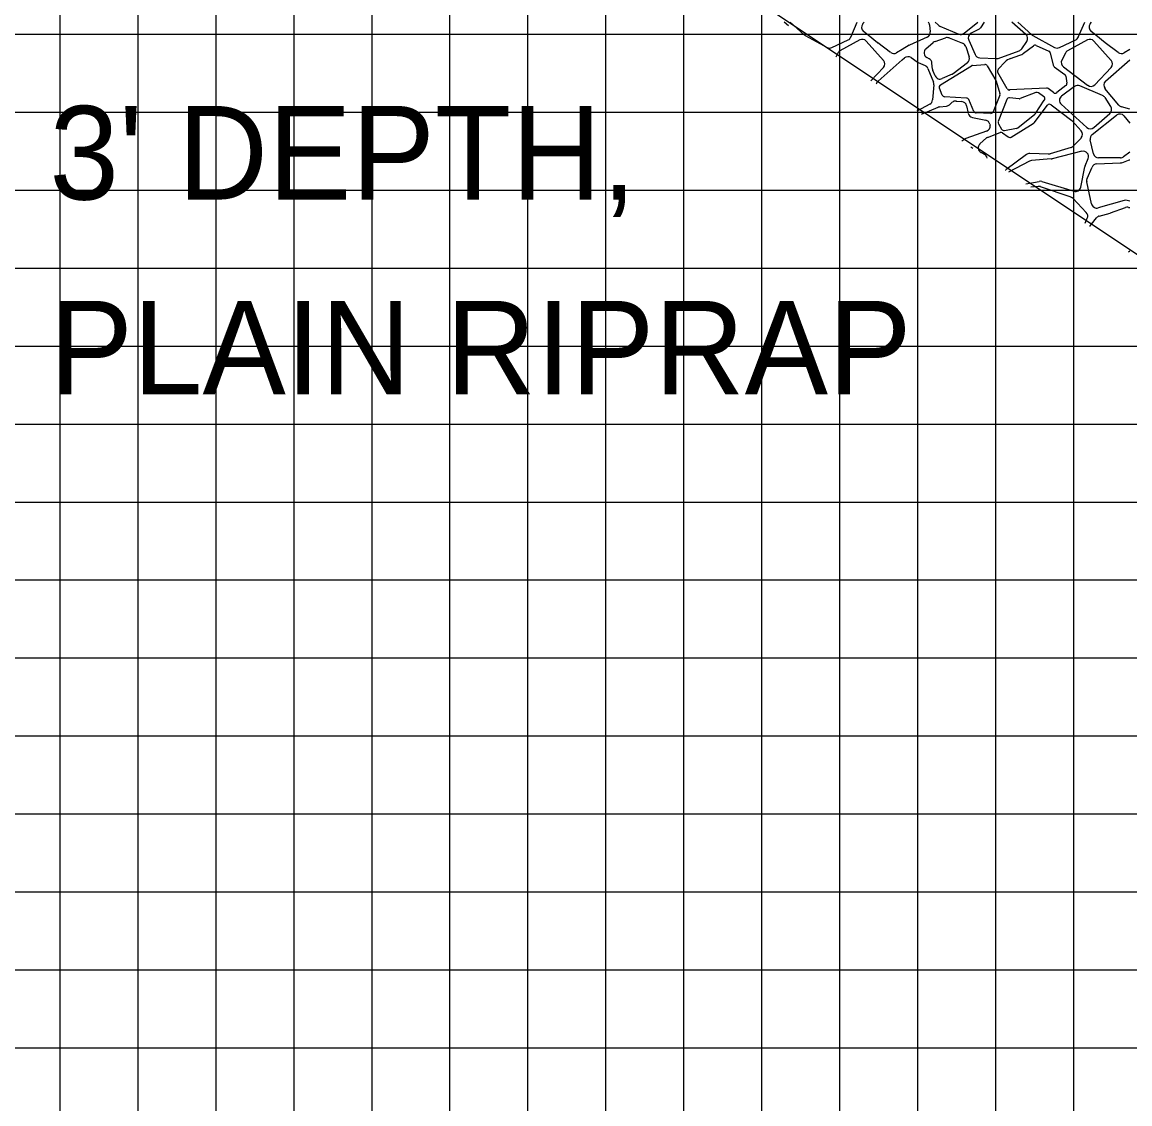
# Model space of a CAD drawing. Extents: x 1770448 to 1770792, y 442591 to 442811.
# Drawn here: x 1770533.55 to 1770547.76, y 442620.95 to 442634.82 of the extents above; entities that cross this region are included whole.
import ezdxf

# ---------------------------------------------------------------- set-up
doc = ezdxf.new("R2010")
doc.units = 0
for name, color, linetype in [('ANNOTATION', 7, 'Continuous'), ('D_Text_Standard', 7, 'Continuous'), ('GRUBBING IN FILL', 7, 'Continuous'), ('MAJOR', 7, 'Continuous'), ('MINOR', 7, 'Continuous')]:
    doc.layers.add(name, color=color, linetype=linetype)

msp = doc.modelspace()

# ---------------------------------------------------------------- linework, layer by layer
at = {"layer": 'ANNOTATION'}
msp.add_lwpolyline([(1770578.203, 442611.606), (1770524.472, 442647.426), (1770523.442, 442648.037), (1770522.53, 442648.443), (1770521.67, 442648.698), (1770521.011, 442648.796)], dxfattribs=at)
at = {"layer": 'GRUBBING IN FILL'}
for p, q in [((1770543.381, 442634.773), (1770543.327, 442634.819)), ((1770543.404, 442634.819), (1770543.585, 442634.657)), ((1770544.182, 442634.627), (1770544.264, 442634.819)), ((1770544.334, 442634.796), (1770544.352, 442634.819)), ((1770544.405, 442634.652), (1770544.345, 442634.7)), ((1770545.192, 442634.784), (1770545.2, 442634.693)), ((1770545.264, 442634.819), (1770545.301, 442634.783)), ((1770545.323, 442634.768), (1770545.567, 442634.667)), ((1770545.636, 442634.677), (1770545.813, 442634.819)), ((1770545.819, 442634.723), (1770545.727, 442634.677)), ((1770545.894, 442634.819), (1770545.845, 442634.746)), ((1770546.426, 442634.661), (1770546.246, 442634.819)), ((1770546.323, 442634.819), (1770546.504, 442634.657)), ((1770547.1, 442634.627), (1770547.183, 442634.819)), ((1770547.253, 442634.796), (1770547.271, 442634.819)), ((1770547.324, 442634.652), (1770547.264, 442634.7)), ((1770543.598, 442634.648), (1770543.877, 442634.495)), ((1770543.939, 442634.493), (1770544.148, 442634.593)), ((1770544.298, 442634.591), (1770544.043, 442634.451)), ((1770544.602, 442634.329), (1770544.381, 442634.576)), ((1770544.525, 442634.555), (1770544.406, 442634.652)), ((1770544.693, 442634.43), (1770544.527, 442634.553)), ((1770545.16, 442634.625), (1770544.937, 442634.525)), ((1770545.144, 442634.476), (1770545.24, 442634.56)), ((1770545.263, 442634.573), (1770545.397, 442634.618)), ((1770545.443, 442634.617), (1770545.616, 442634.55)), ((1770545.695, 442634.589), (1770545.776, 442634.403)), ((1770546.375, 442634.478), (1770546.438, 442634.572)), ((1770546.516, 442634.648), (1770546.796, 442634.495)), ((1770546.858, 442634.493), (1770547.067, 442634.593)), ((1770547.216, 442634.591), (1770546.962, 442634.451)), ((1770547.521, 442634.329), (1770547.3, 442634.576)), ((1770547.444, 442634.555), (1770547.324, 442634.652)), ((1770547.612, 442634.43), (1770547.446, 442634.553)), ((1770544.015, 442634.421), (1770543.988, 442634.368)), ((1770544.842, 442634.47), (1770544.769, 442634.426)), ((1770544.93, 442634.522), (1770544.842, 442634.47)), ((1770545.656, 442634.508), (1770545.702, 442634.374)), ((1770546.074, 442634.355), (1770546.342, 442634.452)), ((1770546.397, 442634.421), (1770546.524, 442634.515)), ((1770546.558, 442634.519), (1770546.721, 442634.447)), ((1770546.74, 442634.424), (1770546.778, 442634.268)), ((1770546.934, 442634.421), (1770546.889, 442634.333)), ((1770547.761, 442634.47), (1770547.687, 442634.426)), ((1770544.531, 442634.062), (1770544.842, 442634.335)), ((1770544.842, 442634.335), (1770544.87, 442634.36)), ((1770544.955, 442634.364), (1770545.033, 442634.309)), ((1770545.045, 442634.302), (1770545.134, 442634.263)), ((1770545.187, 442634.348), (1770545.157, 442634.364)), ((1770545.23, 442634.217), (1770545.223, 442634.294)), ((1770545.678, 442634.298), (1770545.494, 442634.158)), ((1770545.745, 442634.264), (1770545.9, 442634.277)), ((1770545.835, 442634.363), (1770546.047, 442634.351)), ((1770546.074, 442634.214), (1770546.162, 442634.309)), ((1770546.231, 442634.355), (1770546.351, 442634.396)), ((1770547.45, 442634.062), (1770547.761, 442634.335)), ((1770544.44, 442634.068), (1770544.601, 442634.237)), ((1770545.17, 442634.226), (1770545.244, 442634.048)), ((1770545.264, 442634.13), (1770545.236, 442634.197)), ((1770545.332, 442634.014), (1770545.73, 442634.259)), ((1770545.48, 442634.151), (1770545.355, 442634.095)), ((1770545.932, 442634.26), (1770546.044, 442634.07)), ((1770546.188, 442633.966), (1770546.07, 442634.174)), ((1770546.791, 442634.248), (1770546.926, 442634.149)), ((1770546.909, 442634.248), (1770547.22, 442634.01)), ((1770546.94, 442634.127), (1770546.953, 442634.038)), ((1770547.311, 442634.017), (1770547.52, 442634.237)), ((1770545.249, 442634.016), (1770545.231, 442633.821)), ((1770546.047, 442634.063), (1770546.095, 442633.905)), ((1770546.94, 442634.006), (1770546.823, 442633.915)), ((1770547.051, 442633.994), (1770546.886, 442633.871)), ((1770547.412, 442633.878), (1770547.119, 442634.003)), ((1770545.355, 442633.883), (1770545.318, 442633.972)), ((1770545.667, 442633.845), (1770545.385, 442633.862)), ((1770546.094, 442633.882), (1770546.009, 442633.67)), ((1770546.691, 442633.974), (1770546.219, 442633.949)), ((1770546.34, 442633.837), (1770546.219, 442633.849)), ((1770546.557, 442633.915), (1770546.355, 442633.839)), ((1770546.655, 442633.867), (1770546.588, 442633.911)), ((1770546.781, 442633.915), (1770546.714, 442633.967)), ((1770547.619, 442633.755), (1770547.442, 442633.967)), ((1770547.517, 442633.737), (1770547.443, 442633.852)), ((1770545.195, 442633.766), (1770545.027, 442633.677)), ((1770545.109, 442633.647), (1770545.302, 442633.727)), ((1770545.32, 442633.732), (1770545.411, 442633.743)), ((1770545.447, 442633.759), (1770545.484, 442633.791)), ((1770545.535, 442633.807), (1770545.608, 442633.8)), ((1770545.668, 442633.747), (1770545.689, 442633.65)), ((1770545.762, 442633.675), (1770545.696, 442633.825)), ((1770546.184, 442633.827), (1770546.074, 442633.543)), ((1770546.532, 442633.528), (1770546.704, 442633.753)), ((1770546.55, 442633.648), (1770546.664, 442633.82)), ((1770546.752, 442633.759), (1770547.018, 442633.556)), ((1770546.881, 442633.766), (1770547.209, 442633.469)), ((1770547.761, 442633.705), (1770547.654, 442633.733)), ((1770545.742, 442633.597), (1770545.912, 442633.562)), ((1770545.977, 442633.649), (1770545.792, 442633.655)), ((1770546.324, 442633.465), (1770546.543, 442633.641)), ((1770547.276, 442633.377), (1770547.591, 442633.627)), ((1770547.299, 442633.468), (1770547.505, 442633.648)), ((1770547.686, 442633.617), (1770547.761, 442633.525)), ((1770545.924, 442633.42), (1770545.657, 442633.326)), ((1770545.965, 442633.511), (1770545.968, 442633.5)), ((1770546.077, 442633.513), (1770546.117, 442633.446)), ((1770546.152, 442633.429), (1770546.309, 442633.458)), ((1770546.238, 442633.346), (1770546.523, 442633.52)), ((1770547.022, 442633.552), (1770547.137, 442633.427)), ((1770545.643, 442633.319), (1770545.604, 442633.294)), ((1770545.839, 442633.257), (1770545.924, 442633.334)), ((1770545.935, 442633.341), (1770546.096, 442633.403)), ((1770546.129, 442633.399), (1770546.201, 442633.348)), ((1770547.137, 442633.333), (1770547.039, 442633.231)), ((1770547.295, 442633.131), (1770547.252, 442633.308)), ((1770545.896, 442633.123), (1770545.853, 442633.146)), ((1770546.717, 442633.127), (1770546.477, 442633.134)), ((1770547.009, 442633.212), (1770546.739, 442633.13)), ((1770547.147, 442633.163), (1770546.764, 442633.068)), ((1770547.761, 442633.152), (1770547.68, 442633.092)), ((1770545.932, 442633.075), (1770545.932, 442633.076)), ((1770546.434, 442633.12), (1770546.172, 442632.923)), ((1770546.475, 442633.037), (1770546.204, 442632.894)), ((1770546.753, 442633.066), (1770546.501, 442633.045)), ((1770547.187, 442632.975), (1770547.226, 442633.07)), ((1770547.336, 442633), (1770547.638, 442633.013)), ((1770547.64, 442633.079), (1770547.361, 442633.079)), ((1770547.658, 442633.017), (1770547.742, 442633.047)), ((1770547.131, 442632.702), (1770547.183, 442632.962)), ((1770547.213, 442632.815), (1770547.277, 442632.96)), ((1770546.427, 442632.746), (1770546.599, 442632.777)), ((1770546.585, 442632.712), (1770546.493, 442632.702)), ((1770547.007, 442632.574), (1770546.615, 442632.709)), ((1770546.631, 442632.775), (1770547.045, 442632.65)), ((1770547.271, 442632.488), (1770547.208, 442632.773)), ((1770547.202, 442632.379), (1770547.034, 442632.556)), ((1770547.69, 442632.533), (1770547.356, 442632.437)), ((1770547.515, 442632.373), (1770547.707, 442632.441)), ((1770547.761, 442632.523), (1770547.728, 442632.533)), ((1770547.742, 442632.444), (1770547.761, 442632.441)), ((1770547.187, 442632.24), (1770547.215, 442632.305)), ((1770547.271, 442632.229), (1770547.333, 442632.309)), ((1770547.369, 442632.333), (1770547.51, 442632.371)), ((1770547.253, 442632.206), (1770547.271, 442632.229)), ((1770547.761, 442631.88), (1770547.744, 442631.87))]:
    msp.add_line(p, q, dxfattribs=at)
for centre, major_axis, start_param, end_param in [((1770544.388, 442634.754), (0, -0.0683), 4.048343, 5.608444), ((1770545.132, 442634.687), (0, 0.0683), 3.559817, 4.803049), ((1770545.124, 442634.778), (0, 0.0683), 4.803049, 5.35086), ((1770545.349, 442634.831), (0, -0.0683), 5.497787, 5.893869), ((1770545.788, 442634.784), (0, -0.0683), 0.463648, 0.97362), ((1770547.306, 442634.754), (0, -0.0683), 4.048343, 5.608444), ((1770543.63, 442634.708), (0, -0.0683), 5.554357, 5.782172), ((1770544.119, 442634.654), (0, -0.0683), 0.443382, 1.163165), ((1770544.33, 442634.531), (0, 0.0683), 5.44252, 6.785098), ((1770544.363, 442634.599), (0, 0.0683), 5.600869, 5.608444), ((1770544.568, 442634.608), (0, -0.0683), 5.600869, 5.645637), ((1770545.285, 442634.508), (0, 0.0683), 0.321751, 0.71883), ((1770545.418, 442634.553), (0, 0.0683), 5.917129, 6.604936), ((1770545.593, 442634.73), (0, -0.0683), 5.893869, 6.957926), ((1770545.592, 442634.486), (0, 0.0683), 5.039487, 5.917129), ((1770545.757, 442634.616), (0, 0.0683), 0.463648, 1.985303), ((1770546.382, 442634.61), (0, -0.0683), 0.977446, 2.424153), ((1770546.549, 442634.708), (0, -0.0683), 5.554357, 5.782172), ((1770547.038, 442634.654), (0, -0.0683), 0.443382, 1.163165), ((1770547.249, 442634.531), (0, 0.0683), 5.44252, 6.785098), ((1770547.281, 442634.599), (0, 0.0683), 5.600869, 5.608444), ((1770547.487, 442634.608), (0, -0.0683), 5.600869, 5.645637), ((1770543.91, 442634.555), (0, -0.0683), 5.782172, 6.726567), ((1770544.076, 442634.391), (0, 0.0683), 0.501913, 1.108164), ((1770544.734, 442634.485), (0, -0.0683), 5.645637, 6.81814), ((1770544.965, 442634.463), (0, 0.0683), 0.418224, 0.534955), ((1770545.189, 442634.425), (0, -0.0683), 3.860423, 5.799738), ((1770546.318, 442634.516), (0, -0.0683), 0.347767, 0.977446), ((1770546.295, 442634.557), (0, -0.171), 0.333945, 0.641659), ((1770546.544, 442634.488), (0, 0.0342), 5.866747, 6.924845), ((1770546.707, 442634.416), (0, 0.0342), 4.95256, 5.866747), ((1770546.829, 442634.555), (0, -0.0683), 5.782172, 6.726567), ((1770546.995, 442634.391), (0, 0.0683), 0.501913, 1.108164), ((1770547.653, 442634.485), (0, -0.0683), 5.645637, 6.81814), ((1770544.551, 442634.284), (0, -0.0683), 0.810393, 2.300927), ((1770544.915, 442634.308), (0, 0.0683), 5.668522, 7.003256), ((1770545.073, 442634.365), (0, -0.0683), 5.668522, 5.870775), ((1770545.155, 442634.288), (0, 0.0683), 4.803049, 5.799738), ((1770545.637, 442634.352), (0, 0.0683), 3.787712, 5.039487), ((1770545.747, 442634.23), (0, 0.0342), 0.081452, 0.550676), ((1770545.839, 442634.431), (0, -0.0683), 5.126896, 6.226907), ((1770545.903, 442634.243), (0, 0.0342), 5.244893, 6.364637), ((1770546.051, 442634.419), (0, -0.0683), 6.226907, 6.630952), ((1770546.287, 442634.193), (0, 0.171), 0.333945, 0.825917), ((1770546.811, 442634.276), (0, -0.0342), 4.95256, 5.649393), ((1770546.95, 442634.302), (0, 0.0683), 1.108164, 2.48948), ((1770547.47, 442634.284), (0, -0.0683), 0.810393, 2.300927), ((1770545.107, 442634.2), (0, 0.0683), 5.104729, 5.870775), ((1770545.298, 442634.224), (0, -0.0683), 4.803049, 5.120538), ((1770545.327, 442634.157), (0, -0.0683), 5.120538, 6.699624), ((1770545.453, 442634.213), (0, -0.0683), 0.416439, 0.646119), ((1770546.099, 442634.19), (0, -0.0342), 3.967509, 5.232357), ((1770546.906, 442634.121), (0, 0.0342), 4.865038, 5.649393), ((1770544.576, 442634.011), (0, -0.0683), 3.861663, 4.542823), ((1770545.181, 442634.022), (0, 0.0683), 4.621729, 5.104729), ((1770545.349, 442633.985), (0, -0.0342), 3.692268, 5.10718), ((1770546.014, 442634.053), (0, 0.0342), 5.00783, 5.244893), ((1770546.92, 442634.033), (0, 0.0342), 3.796699, 4.865038), ((1770547.092, 442633.94), (0, 0.0683), 5.881372, 6.922099), ((1770547.262, 442634.064), (0, -0.0683), 5.631073, 7.093578), ((1770547.495, 442634.011), (0, -0.0683), 3.861663, 5.40978), ((1770545.387, 442633.896), (0, -0.0342), 5.10718, 6.225111), ((1770545.665, 442633.811), (0, 0.0342), 5.126896, 6.225111), ((1770546.062, 442633.895), (0, 0.0342), 4.331883, 5.00783), ((1770546.215, 442633.815), (0, 0.0342), 6.185932, 7.487587), ((1770546.218, 442633.983), (0, -0.0342), 5.232357, 6.335377), ((1770546.343, 442633.871), (0, -0.0342), 6.185932, 6.640689), ((1770546.569, 442633.883), (0, 0.0342), 5.695183, 6.640689), ((1770546.636, 442633.838), (0, -0.0342), 0.982794, 2.55359), ((1770546.693, 442633.94), (0, 0.0342), 5.62749, 6.335377), ((1770546.802, 442633.942), (0, -0.0342), 5.62749, 6.938291), ((1770546.926, 442633.816), (0, 0.0683), 0.638914, 2.406418), ((1770547.385, 442633.815), (0, 0.0683), 5.287694, 5.881372), ((1770545.163, 442633.827), (0, -0.0683), 0.489957, 1.480136), ((1770545.328, 442633.664), (0, 0.0683), 0.124355, 0.394791), ((1770545.402, 442633.811), (0, -0.0683), 0.124355, 0.704494), ((1770545.529, 442633.739), (0, 0.0683), 6.183517, 6.987679), ((1770545.601, 442633.732), (0, 0.0683), 4.928939, 6.183517), ((1770546.731, 442633.732), (0, 0.0342), 5.630339, 7.201135), ((1770547.46, 442633.7), (0, -0.0683), 0.719883, 2.146101), ((1770547.672, 442633.799), (0, -0.0683), 5.40978, 6.025862), ((1770545.136, 442633.584), (0, 0.0683), 0.394791, 0.726629), ((1770545.756, 442633.664), (0, -0.0683), 4.928939, 6.08014), ((1770545.793, 442633.689), (0, -0.0342), 5.126896, 6.25041), ((1770545.899, 442633.495), (0, 0.0683), 4.941621, 6.08014), ((1770545.978, 442633.683), (0, -0.0342), 6.25041, 7.473475), ((1770546.522, 442633.667), (0, -0.0342), 0.676737, 0.982794), ((1770546.997, 442633.529), (0, 0.0342), 5.459199, 5.630339), ((1770547.633, 442633.573), (0, 0.0683), 5.401291, 6.952921), ((1770545.901, 442633.484), (0, 0.0683), 3.480291, 4.941621), ((1770546.106, 442633.53), (0, 0.0342), 1.204402, 2.105751), ((1770546.146, 442633.463), (0, -0.0342), 5.247344, 6.461278), ((1770546.303, 442633.491), (0, -0.0342), 0.178093, 0.676737), ((1770546.505, 442633.549), (0, -0.0342), 0.547562, 0.91795), ((1770547.087, 442633.381), (0, 0.0683), 3.950796, 5.459199), ((1770547.254, 442633.519), (0, -0.0683), 5.54801, 7.003068), ((1770545.68, 442633.261), (0, 0.0683), 0.338698, 0.570383), ((1770545.947, 442633.309), (0, 0.0342), 0.369906, 0.736656), ((1770546.109, 442633.372), (0, 0.0342), 5.662936, 6.653091), ((1770546.221, 442633.375), (0, -0.0342), 5.662936, 6.830748), ((1770547.319, 442633.324), (0, -0.0683), 3.811328, 4.949439), ((1770545.698, 442633.151), (0, 0.0683), 5.469865, 5.923398), ((1770545.885, 442633.206), (0, -0.0683), 3.878249, 5.800672), ((1770546.475, 442633.066), (0, 0.0683), 6.255795, 6.928761), ((1770546.719, 442633.196), (0, -0.0683), 6.255795, 6.578122), ((1770546.989, 442633.278), (0, -0.0683), 0.294937, 0.809203), ((1770547.163, 442633.096), (0, -0.0683), 1.177705, 3.383486), ((1770547.361, 442633.147), (0, -0.0683), 4.949439, 6.284735), ((1770545.865, 442633.063), (0, 0.0683), 4.915434, 5.800672), ((1770546.507, 442632.977), (0, 0.0683), 0.083141, 0.485227), ((1770546.747, 442633.134), (0, -0.0683), 0.083141, 0.241894), ((1770547.339, 442632.932), (0, 0.0683), 0.042528, 1.152572), ((1770547.635, 442633.082), (0, -0.0683), 0.042528, 0.339293), ((1770547.64, 442633.147), (0, -0.0683), 0.001549, 0.632145), ((1770547.764, 442632.982), (0, 0.0683), 0.046753, 0.339293), ((1770546.131, 442632.977), (0, -0.0683), 0.549654, 0.645576), ((1770547.25, 442632.949), (0, 0.0683), 1.177705, 1.37369), ((1770546.593, 442632.645), (0, 0.0683), 5.950458, 6.397059), ((1770546.611, 442632.71), (0, 0.0683), 5.991139, 6.460411), ((1770547.064, 442632.716), (0, -0.0683), 5.991139, 7.656876), ((1770547.275, 442632.788), (0, -0.0683), 4.294165, 4.928939), ((1770546.984, 442632.509), (0, 0.0683), 5.472885, 5.950458), ((1770547.337, 442632.503), (0, -0.0683), 4.928939, 6.561485), ((1770547.709, 442632.467), (0, 0.0683), 6.004886, 6.561485), ((1770547.73, 442632.377), (0, 0.0683), 6.110994, 6.626209), ((1770547.153, 442632.332), (0, -0.0683), 1.163165, 2.331293), ((1770547.387, 442632.267), (0, 0.0683), 0.266252, 0.90675), ((1770547.492, 442632.437), (0, -0.0683), 0.266252, 0.343024), ((1770547.306, 442632.164), (0, -0.0683), 4.048343, 4.166099)]:
    msp.add_ellipse(centre, major_axis=major_axis, ratio=0.99895, start_param=start_param, end_param=end_param, dxfattribs=at)
at = {"layer": 'MAJOR'}
for p, q in [((1770534.041, 442608.665), (1770534.041, 442658.665)), ((1770544.041, 442608.665), (1770544.041, 442658.665)), ((1770474.041, 442633.665), (1770754.041, 442633.665)), ((1770474.041, 442628.665), (1770754.041, 442628.665)), ((1770474.041, 442623.665), (1770754.041, 442623.665))]:
    msp.add_line(p, q, dxfattribs=at)
at = {"layer": 'MINOR'}
for p, q in [((1770535.041, 442608.665), (1770535.041, 442658.665)), ((1770536.041, 442608.665), (1770536.041, 442658.665)), ((1770537.041, 442608.665), (1770537.041, 442658.665)), ((1770538.041, 442608.665), (1770538.041, 442658.665)), ((1770539.041, 442608.665), (1770539.041, 442658.665)), ((1770540.041, 442608.665), (1770540.041, 442658.665)), ((1770541.041, 442608.665), (1770541.041, 442658.665)), ((1770542.041, 442608.665), (1770542.041, 442658.665)), ((1770543.041, 442608.665), (1770543.041, 442658.665)), ((1770545.041, 442608.665), (1770545.041, 442658.665)), ((1770546.041, 442608.665), (1770546.041, 442658.665)), ((1770547.041, 442608.665), (1770547.041, 442658.665)), ((1770474.041, 442634.665), (1770754.041, 442634.665)), ((1770474.041, 442632.665), (1770754.041, 442632.665)), ((1770474.041, 442631.665), (1770754.041, 442631.665)), ((1770474.041, 442630.665), (1770754.041, 442630.665)), ((1770474.041, 442629.665), (1770754.041, 442629.665)), ((1770474.041, 442627.665), (1770754.041, 442627.665)), ((1770474.041, 442626.665), (1770754.041, 442626.665)), ((1770474.041, 442625.665), (1770754.041, 442625.665)), ((1770474.041, 442624.665), (1770754.041, 442624.665)), ((1770474.041, 442622.665), (1770754.041, 442622.665)), ((1770474.041, 442621.665), (1770754.041, 442621.665))]:
    msp.add_line(p, q, dxfattribs=at)

# ---------------------------------------------------------------- texts
at = {"layer": 'D_Text_Standard'}
for s, p in [("3' DEPTH, ", (1770533.903, 442632.544)), ('PLAIN RIPRAP', (1770533.903, 442630.044))]:
    msp.add_text(s, height=1.2, dxfattribs=at).set_placement(p)

doc.saveas('drawing.dxf')
